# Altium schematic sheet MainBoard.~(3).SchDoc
size A4
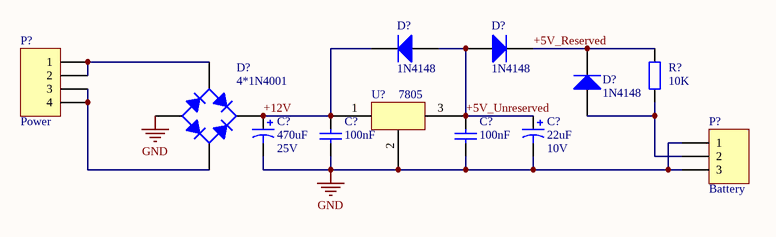
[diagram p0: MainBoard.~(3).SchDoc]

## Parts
(Parts that share a designator on the sheet are numbered #1, #2 ... from top to bottom, then left to right.)
C?#1  25V  value 470uF  [RB7.6-15]
C?#2  10V  value 22uF  [RB7.6-15]
C?#3  value 100nF  [RAD-0.3]  (hidden comment: Cap)
C?#4  value 100nF  [RAD-0.3]  (hidden comment: Cap)
D?#1  1N4148  [DO-35]
D?#2  1N4148  [DO-35]
D?#3  4*1N4001  [D-38]
D?#4  1N4148  [DO-35]
P?#1  Power  [HDR1X4]
P?#2  Battery  [HDR1X3]
R?  value 10K  [AXIAL-0.4]  (hidden comment: Res2)
U?  7805

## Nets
GND: C?#1.2 C?#2.2 C?#3.1 C?#4.1 D?#3.3(A) P?#2.1 P?#2.3 U?.2(GND)
+5V_Reserved: D?#2.2(K) D?#4.2(K) R?.2
+5V_Unreserved: C?#2.1 C?#4.2 D?#1.1(A) D?#2.1(A) U?.3(Out)
+12V: C?#1.1 C?#3.2 D?#1.2(K) D?#3.1(K) U?.1(In)
NetD?#3_2: D?#3.2(C) P?#1.3 P?#1.4
NetD?#3_4: D?#3.4(C) P?#1.1 P?#1.2
NetD?#4_1: D?#4.1(A) P?#2.2 R?.1

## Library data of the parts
C?#1 C?#2 = Cap Pol1: Polarized Capacitor (Radial)
C?#3 C?#4 = Cap: Capacitor
D?#1 D?#2 D?#4 = Diode 1N4148: High Conductance Fast Diode
D?#3 = Bridge1: Full Wave Diode Bridge
P?#1 = Header 4: Header, 4-Pin
P?#2 = Header 3: Header, 3-Pin
R? = Res2: Resistor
